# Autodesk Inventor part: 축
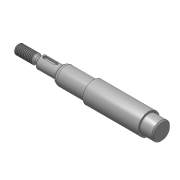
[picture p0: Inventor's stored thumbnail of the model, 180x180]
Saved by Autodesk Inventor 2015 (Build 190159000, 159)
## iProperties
Created: 2015-11
Part Number: 축
Material: 강철, 연강
Document SubType Name: Modeling
Designer: mduedu
Density: 1 g/cm^3
Appearance: 강철
Author: mduedu
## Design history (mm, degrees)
sketch "스케치1"
  geometry: L1 (-86, 0)-(86, 0); L2 (-86, 0)-(-86, 4); L3 (-86, 4)-(-70.732, 4); L4 (-70.732, 4)-(-69, 3); L5 (-69, 3)-(-67, 3); L6 (-67, 3)-(-67, 5); L7 (-67, 5)-(-49, 5); L8 (-49, 5)-(-49, 6.55); L9 (-47.355, 7.5)-(-23, 7.5); L10 (-23, 7.5)-(-23, 9); L11 (0, 0)-(0, 9); L12 (86, 4)-(70.732, 4); L13 (70.732, 4)-(69, 3); L14 (69, 3)-(67, 3); L15 (67, 3)-(67, 5); L16 (67, 5)-(49, 5); L17 (23, 7.5)-(23, 9); L18 (86, 0)-(86, 4); L19 (-23, 9)-(23, 9); L20 (-49, 6.55)-(-47.355, 7.5); L21 (47.355, 7.5)-(23, 7.5); L22 (49, 6.55)-(47.355, 7.5); L23 (49, 5)-(49, 6.55); 1 further point
  constraints: 46 end point, 10 symmetric about line, 6 perpendicular, 5 parallel, 2 midpoint, 1 coincident, 1 horizontal
  dimensions: "d0" = 172 distance of L1.start L1.end (derived); "d1" = 8 diameter of L3 L1; "d2" = 30 deg angle of L4 L5; "d3" = 6 diameter of L5 L1; "d4" = 10 diameter of L7 L1; "d5" = 15 diameter of L9 L1; "d6" = 18 diameter of L19 L1; "d8" = 18 distance of L6.end L7.end; "d9" = 46 distance of L10.end L17.end; "d10" = 2 distance of L4.end L5.end; "d11" = 17 distance from line of L4.end L2; "d16" = 13.1 diameter of L8.end L1; "d17" = 30 deg angle of L20 L9; "d18" = 26 distance between parallel lines of L10 L8
revolve "회전1" sketch "스케치1" stored, may be unused: angle "d12" = 90 deg
chamfer "모따기1" distance "d13" = 1; stored, may be unused: second distance "d14" = 2, angle "d15" = 45 deg
fillet "모깎기3" dims "d35" = 4
node "작업 평면1"
sketch "스케치2" dims "d23" = 12
  geometry: L1 (-5.5, 1.5)-(3.5, 1.5); L2 (3.5, 1.5)-(3.5, -1.5); L3 (3.5, -1.5)-(-5.5, -1.5); L4 (-5.5, -1.5)-(-5.5, 1.5); L5 (-9, -4)-(-9, 4) reference; 3 further points
  constraints: 8 end point, 2 midpoint, 2 parallel, 2 vertical alignment, 1 horizontal, 1 perpendicular, 4 other
  dimensions: "d21" = 3 distance between parallel lines of L3 L1; "d24" = 2 dimension on L5
extrude "돌출1" cut sketch "스케치2" distance "d25" = 1.8; taper "d26" = 0 deg
feature "스레드1" dims "d27" = 10, "d28" = 0
feature "스레드2" dims "d29" = 10, "d30" = 0
chamfer "모따기2" distance "d31" = 1; stored, may be unused: second distance "d32" = 2, angle "d33" = 45 deg
fillet "모깎기2" dims "d34" = 0.3
node "작업 평면2"
sketch "스케치3"
  geometry: C1 r 7.5 at (0, 0) reference; 1 further point
extrude "돌출2" cut sketch "스케치3" stored distance "d37" = 10; taper "d38" = 0 deg
chamfer "모따기3" distance "d39" = 1; stored, may be unused: second distance "d40" = 2, angle "d41" = 45 deg
node "솔리드1"
mirror "대칭1"
node "절단 모서리 투영1"
other parameters: "d36" = 11
